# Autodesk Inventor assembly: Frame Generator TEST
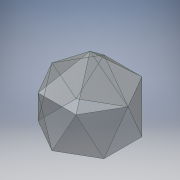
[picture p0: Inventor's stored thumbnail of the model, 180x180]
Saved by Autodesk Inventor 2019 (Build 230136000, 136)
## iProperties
Created: 2018-12
Part Number: Frame Generator TEST
Document SubType Name: Assembly
Designer: Synergysoft
Author: Synergysoft
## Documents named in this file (2)
- D:\Karntarat T\06.MFG_Autodesk Inventor file\01.PPT Training summary\INV01\INV-01 FILE\INV-01 for Trainning\00.Practice\Frame Generator TEST.iam
- D:\Karntarat T\06.MFG_Autodesk Inventor file\01.PPT Training summary\INV01\INV-01 FILE\INV-01 for Trainning\00.Practice\Plane 3 point.ipt
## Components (1 placed, 1 different names)
1. Plane 3 point:1
